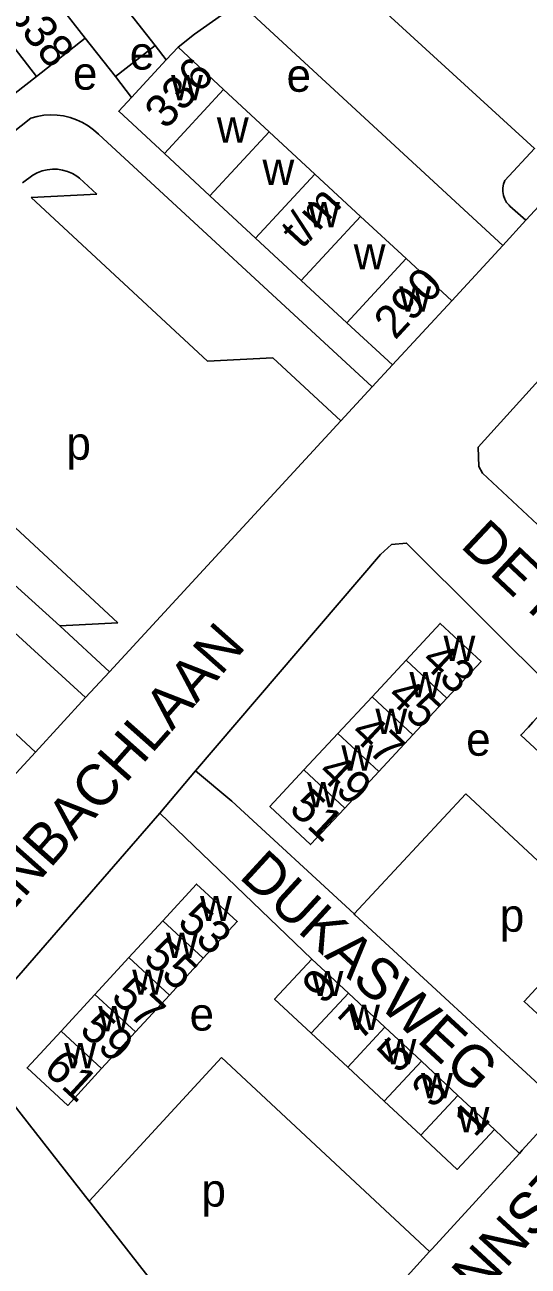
# Model space of a CAD drawing. Extents: x 159045 to 160918, y 380454 to 382516.
# Drawn here: x 159725.3 to 159786.4, y 381546.5 to 381697.2 of the extents above; entities that cross this region are included whole.
import ezdxf

# ---------------------------------------------------------------- set-up
doc = ezdxf.new("R2010")
doc.units = 0
for name, color, linetype in [('BLT_Basislijn', 7, 'Continuous'), ('BLT_Bebouwing', 7, 'Continuous'), ('BLT_Centroide', 7, 'Continuous'), ('BLT_Huisnummer', 7, 'Continuous'), ('BLT_Huisnummer_ tussenligend', 7, 'Continuous'), ('BLT_Huisnummer_reeks', 7, 'Continuous'), ('BLT_Onderverdeling_panden', 7, 'Continuous'), ('BLT_Straatnaam', 7, 'Continuous')]:
    doc.layers.add(name, color=color, linetype=linetype)

msp = doc.modelspace()

# ---------------------------------------------------------------- linework, layer by layer
at = {"layer": 'BLT_Basislijn'}
for p, q in [((159786.12, 381673.44), (159813.87, 381703.6)), ((159742.44, 381692.91), (159741.09, 381694.67)), ((159738.21, 381688.35), (159736.27, 381690.89)), ((159734.21, 381683.9), (159767.46, 381653.22)), ((159731.9, 381678.57), (159734.01, 381676.61)), ((159726.05, 381676.19), (159734.01, 381676.61)), ((159726.05, 381676.19), (159747.45, 381656.35)), ((159784.17, 381675.15), (159786.12, 381673.44)), ((159783.3, 381670.38), (159786.12, 381673.44)), ((159777.11, 381663.65), (159783.3, 381670.38)), ((159747.45, 381656.35), (159755.38, 381656.76)), ((159755.38, 381656.76), (159763.65, 381649.09)), ((159767.46, 381653.22), (159769.91, 381655.88)), ((159763.65, 381649.09), (159767.46, 381653.22)), ((159735.53, 381618.63), (159763.65, 381649.09)), ((159710.15, 381641.71), (159729.51, 381624.22)), ((159717.64, 381642.1), (159736.54, 381624.59)), ((159729.51, 381624.22), (159736.54, 381624.59)), ((159729.51, 381624.22), (159735.53, 381618.63)), ((159732.65, 381615.51), (159735.53, 381618.63)), ((159726.55, 381608.91), (159732.65, 381615.51)), ((159741.64, 381601.47), (159746, 381606.64)), ((159765.26, 381589.25), (159778.83, 381603.82)), ((159803.8, 381580.61), (159778.83, 381603.82)), ((159760.12, 381583.78), (159741.64, 381601.47)), ((159765.26, 381589.25), (159765.35, 381589.16)), ((159765.35, 381589.16), (159790.52, 381565.9)), ((159733.09, 381554.4), (159749.14, 381571.82)), ((159774.4, 381548.27), (159749.14, 381571.82)), ((159785.32, 381560.2), (159782.3, 381563.11)), ((159774.73, 381548.63), (159785.32, 381560.2)), ((159733.09, 381554.4), (159733.27, 381554.16)), ((159774.4, 381548.27), (159774.73, 381548.63))]:
    msp.add_line(p, q, dxfattribs=at)
for points in [[(159765.48, 381702.01), (159787.17, 381682.15), (159783.55, 381678.28)], [(159743.87, 381694.45), (159745.88, 381696.05), (159751.35, 381699.86), (159783.3, 381670.38)], [(159681.01, 381652.02), (159686, 381654.17), (159725.99, 381685.84)], [(159725.99, 381685.84), (159726.77, 381686.05), (159727.57, 381686.18), (159728.38, 381686.24), (159729.18, 381686.21), (159729.98, 381686.1), (159730.77, 381685.91), (159731.53, 381685.65), (159732.26, 381685.31), (159732.96, 381684.9), (159733.61, 381684.43), (159734.21, 381683.9)], [(159724.99, 381678), (159726.22, 381678.93), (159726.78, 381679.22), (159727.37, 381679.44), (159727.98, 381679.58), (159728.61, 381679.65), (159729.24, 381679.63), (159729.86, 381679.54), (159730.46, 381679.37), (159731.04, 381679.12), (159731.59, 381678.8), (159731.9, 381678.57)], [(159783.55, 381678.28), (159783.39, 381677.84), (159783.31, 381677.38), (159783.31, 381676.92), (159783.39, 381676.46), (159783.54, 381676.02), (159783.77, 381675.62), (159784.06, 381675.26), (159784.17, 381675.15)], [(159797.22, 381627.45), (159780.83, 381642.76), (159780.4, 381643.57), (159780.33, 381645.92), (159803.87, 381671.93)], [(159693.34, 381639.54), (159699.35, 381645.33), (159700.15, 381645.22), (159732.65, 381615.51)], [(159746, 381606.64), (159768.44, 381632.88), (159769.79, 381634.08), (159771.62, 381634.27), (159790.07, 381615.88)], [(159746, 381606.64), (159750.41, 381602.93), (159765.26, 381589.25)], [(159741.64, 381601.47), (159722.92, 381579.91), (159719.1, 381574.93), (159719.39, 381572.57), (159722.79, 381567.55), (159733.09, 381554.4)], [(159801.33, 381577.88), (159795.33, 381583.42), (159796.15, 381585.26), (159793.91, 381587.33), (159785.89, 381578.65), (159793.25, 381571.84), (159797.38, 381576.25), (159798.77, 381576.27), (159799.41, 381575.74)], [(159785.32, 381560.2), (159785.67, 381560.59), (159790.52, 381565.9)], [(159733.27, 381554.16), (159752.77, 381529.25), (159753.89, 381528.65), (159756.67, 381528.87), (159757.45, 381529.55), (159774.4, 381548.27)]]:
    msp.add_lwpolyline(points, dxfattribs=at)
at = {"layer": 'BLT_Bebouwing'}
for p, q in [((159731.64, 381706.66), (159741.09, 381694.67)), ((159732.61, 381695.55), (159726.69, 381690.91)), ((159736.27, 381690.89), (159732.61, 381695.55)), ((159741.09, 381694.67), (159736.27, 381690.89)), ((159742.44, 381692.91), (159743.87, 381694.45)), ((159743.87, 381694.45), (159749.41, 381689.32)), ((159738.21, 381688.35), (159742.44, 381692.91)), ((159726.69, 381690.91), (159720.76, 381686.27)), ((159749.41, 381689.32), (159754.95, 381684.18)), ((159754.95, 381684.18), (159760.49, 381679.05)), ((159747.75, 381676.41), (159742.21, 381681.54)), ((159760.49, 381679.05), (159766.03, 381673.92)), ((159753.29, 381671.28), (159747.75, 381676.41)), ((159766.03, 381673.92), (159771.57, 381668.79)), ((159758.83, 381666.15), (159753.29, 381671.28)), ((159771.57, 381668.79), (159777.11, 381663.65)), ((159764.37, 381661.01), (159758.83, 381666.15)), ((159777.11, 381663.65), (159769.91, 381655.88)), ((159769.91, 381655.88), (159764.37, 381661.01)), ((159767.43, 381615.62), (159771.56, 381620.07)), ((159763.29, 381611.17), (159767.43, 381615.62)), ((159776.52, 381615.45), (159772.39, 381611)), ((159721.02, 381614.01), (159726.55, 381608.91)), ((159759.15, 381606.73), (159763.29, 381611.17)), ((159772.39, 381611), (159768.25, 381606.56)), ((159726.55, 381608.91), (159719.46, 381601.22)), ((159768.25, 381606.56), (159764.11, 381602.11)), ((159737.89, 381583.96), (159742.01, 381588.42)), ((159733.78, 381579.49), (159737.89, 381583.96)), ((159746.94, 381583.87), (159742.83, 381579.41)), ((159760.12, 381583.78), (159764.56, 381579.65)), ((159764.56, 381579.65), (159768.99, 381575.51)), ((159729.66, 381575.03), (159733.78, 381579.49)), ((159742.83, 381579.41), (159738.71, 381574.94)), ((159768.99, 381575.51), (159773.43, 381571.38)), ((159738.71, 381574.94), (159734.59, 381570.48)), ((159760.04, 381574.8), (159764.47, 381570.66)), ((159764.47, 381570.66), (159768.9, 381566.53)), ((159773.43, 381571.38), (159777.86, 381567.24)), ((159768.9, 381566.53), (159773.34, 381562.39)), ((159777.86, 381567.24), (159782.3, 381563.11))]:
    msp.add_line(p, q, dxfattribs=at)
for points in [[(159742.21, 381681.54), (159736.67, 381686.68), (159738.21, 381688.35)], [(159771.56, 381620.07), (159775.7, 381624.51), (159780.66, 381619.89), (159776.52, 381615.45)], [(159790.07, 381615.88), (159786.95, 381612.52), (159786.41, 381611.94), (159785.49, 381610.96), (159789.93, 381606.84)], [(159764.11, 381602.11), (159759.97, 381597.67), (159755.02, 381602.29), (159759.15, 381606.73)], [(159742.01, 381588.42), (159746.13, 381592.88), (159751.06, 381588.33), (159746.94, 381583.87)], [(159760.12, 381583.78), (159755.6, 381578.93), (159760.04, 381574.8)], [(159734.59, 381570.48), (159730.48, 381566.01), (159725.54, 381570.56), (159729.66, 381575.03)], [(159773.34, 381562.39), (159773.88, 381561.89), (159777.77, 381558.26), (159782.3, 381563.11)]]:
    msp.add_lwpolyline(points, dxfattribs=at)
at = {"layer": 'BLT_Onderverdeling_panden'}
for p, q in [((159732.61, 381695.55), (159726.02, 381703.97)), ((159726.69, 381690.91), (159720.1, 381699.33)), ((159742.21, 381681.54), (159749.41, 381689.32)), ((159747.75, 381676.41), (159754.95, 381684.18)), ((159753.29, 381671.28), (159760.49, 381679.05)), ((159758.83, 381666.15), (159766.03, 381673.92)), ((159764.37, 381661.01), (159771.57, 381668.79)), ((159776.52, 381615.45), (159771.56, 381620.07)), ((159772.39, 381611), (159767.43, 381615.62)), ((159768.25, 381606.56), (159763.29, 381611.17)), ((159764.11, 381602.11), (159759.15, 381606.73)), ((159746.94, 381583.87), (159742.01, 381588.42)), ((159742.83, 381579.41), (159737.89, 381583.96)), ((159760.04, 381574.8), (159764.56, 381579.65)), ((159738.71, 381574.94), (159733.78, 381579.49)), ((159764.47, 381570.66), (159768.99, 381575.51)), ((159734.59, 381570.48), (159729.66, 381575.03)), ((159768.9, 381566.53), (159773.43, 381571.38)), ((159773.34, 381562.39), (159777.86, 381567.24))]:
    msp.add_line(p, q, dxfattribs=at)

# ---------------------------------------------------------------- texts
at = {"layer": 'BLT_Centroide'}
for s, p in [('e', (159738.01, 381691.73)), ('e', (159731.11, 381689.29)), ('w', (159743.03, 381688)), ('e', (159757.05, 381689.04)), ('w', (159748.58, 381682.86)), ('w', (159754.12, 381677.73)), ('w', (159759.66, 381672.59)), ('w', (159765.2, 381667.47)), ('w', (159770.73, 381662.34)), ('p', (159730.31, 381644.38)), ('w', (159776.11, 381619.97)), ('w', (159771.98, 381615.53)), ('w', (159767.84, 381611.09)), ('e', (159778.86, 381608.46)), ('w', (159763.7, 381606.66)), ('w', (159759.56, 381602.19)), ('w', (159746.54, 381588.38)), ('p', (159782.94, 381587.1)), ('w', (159742.41, 381583.91)), ('w', (159738.3, 381579.44)), ('w', (159760.08, 381579.28)), ('e', (159745.27, 381575.1)), ('w', (159764.52, 381575.16)), ('w', (159734.18, 381575)), ('w', (159730.07, 381570.53)), ('w', (159768.95, 381571.02)), ('w', (159773.38, 381566.89)), ('w', (159777.81, 381562.75)), ('p', (159746.71, 381553.74))]:
    msp.add_text(s, height=4, dxfattribs=at).set_placement(p)
at = {"layer": 'BLT_Huisnummer'}
for s, rotation, p in [('43', 316.8488, (159773.23, 381619.79)), ('47', 316.8426, (159764.65, 381611)), ('51', 316.8488, (159757.21, 381601.87)), ('53', 317.3128, (159743.64, 381588.08)), ('57', 317.3191, (159735.58, 381579.01)), ('9', 47.0044, (159761.5, 381578.12)), ('5', 47.0044, (159770.63, 381569.75)), ('61', 317.3254, (159727.36, 381570.25)), ('1', 47.0103, (159779.89, 381562.02))]:
    msp.add_text(s, height=4, rotation=rotation, dxfattribs=at).set_placement(p)
at = {"layer": 'BLT_Huisnummer_ tussenligend'}
for s, rotation, p in [('45', 316.8488, (159769.08, 381615.5)), ('49', 316.8426, (159760.67, 381606.24)), ('55', 317.3128, (159739.5, 381583.78)), ('7', 47.0044, (159766.02, 381573.73)), ('59', 317.3191, (159731.76, 381575.01)), ('3', 47.0103, (159774.82, 381565.53))]:
    msp.add_text(s, height=4, rotation=rotation, dxfattribs=at).set_placement(p)
at = {"layer": 'BLT_Huisnummer_reeks'}
for s, rotation, p in [('338', 308.0639, (159722.89, 381698.67)), ('336', 47.1916, (159742.39, 381684.34)), ('t/m', 47.1882, (159758.9, 381669.84)), ('290', 47.1876, (159770.23, 381658.82))]:
    msp.add_text(s, height=4, rotation=rotation, dxfattribs=at).set_placement(p)
at = {"layer": 'BLT_Straatnaam'}
for s, rotation, p in [('DE FALLASTRAAT', 316.7776, (159778.02, 381633.85)), ('OFFENBACHLAAN', 48.4522, (159713.32, 381577.75)), ('DUKASWEG', 317.3808, (159751.15, 381593.69)), ('SCHUMANNSTRAAT', 47.2729, (159760.73, 381521.29))]:
    msp.add_text(s, height=5, rotation=rotation, dxfattribs=at).set_placement(p)

doc.saveas('drawing.dxf')
